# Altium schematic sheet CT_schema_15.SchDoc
size 391 x 385 mm
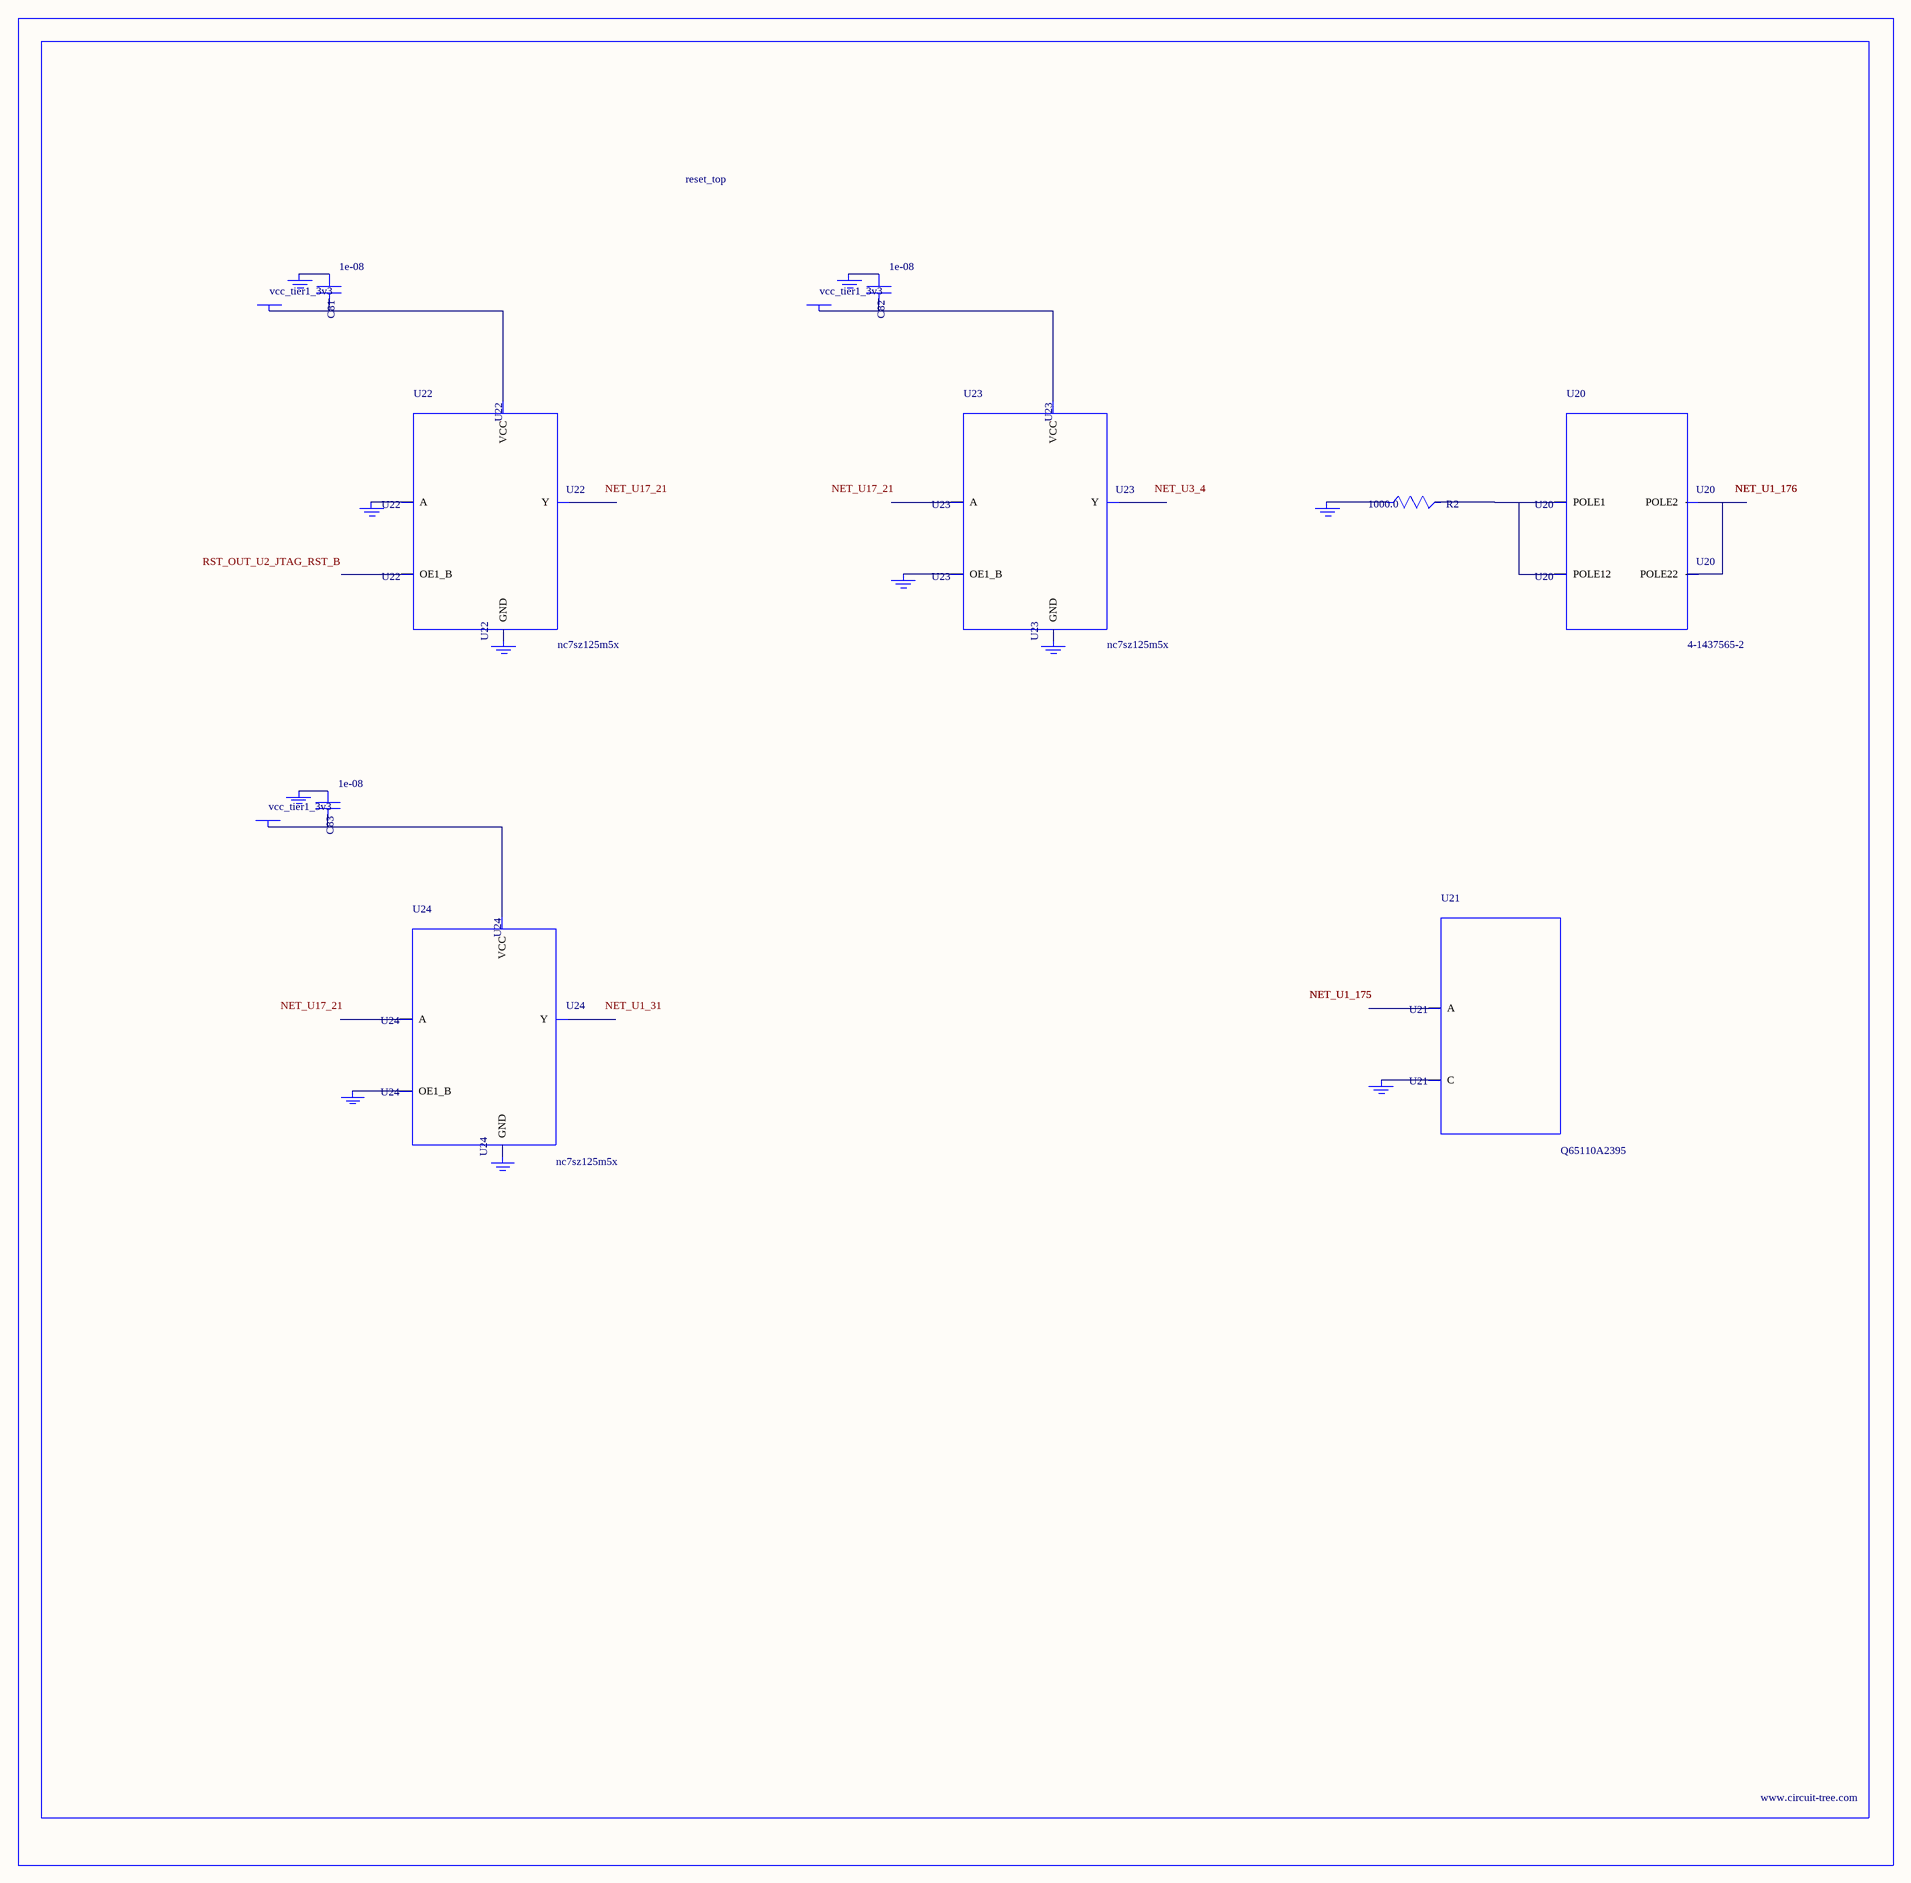
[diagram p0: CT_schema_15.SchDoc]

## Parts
BORDER14  (no value)
C81  1e-08  [C0402]
C82  1e-08  [C0402]
C83  1e-08  [C0402]
GND_INSTANCE_14_0  (no value)
GND_INSTANCE_14_1  (no value)
GND_INSTANCE_14_2  (no value)
GND_INSTANCE_14_3  (no value)
GND_INSTANCE_14_4  (no value)
GND_INSTANCE_14_5  (no value)
GND_INSTANCE_14_6  (no value)
GND_INSTANCE_14_7  (no value)
GND_INSTANCE_14_8  (no value)
GND_INSTANCE_14_9  (no value)
GND_INSTANCE_14_10  (no value)
POWER_INSTANCE_14_0  vcc_tier1_3v3
POWER_INSTANCE_14_1  vcc_tier1_3v3
POWER_INSTANCE_14_2  vcc_tier1_3v3
R2  1000.0  [R0603]
U20  4-1437565-2  [SW_4-1437565-2]
U21  Q65110A2395  [LGM67K-G1J2-24-Z]
U22  nc7sz125m5x  [NC7SZ125M5X]
U23  nc7sz125m5x  [NC7SZ125M5X]
U24  nc7sz125m5x  [NC7SZ125M5X]

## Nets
NetC81_1: C81.1 GND_INSTANCE_14_2.0(GND)
NetC81_2: C81.2 POWER_INSTANCE_14_0.0(PWR) U22.5(VCC)
NetC82_1: C82.1 GND_INSTANCE_14_5.0(GND)
NetC82_2: C82.2 POWER_INSTANCE_14_1.0(PWR) U23.5(VCC)
NetC83_1: C83.1 GND_INSTANCE_14_8.0(GND)
NetC83_2: C83.2 POWER_INSTANCE_14_2.0(PWR) U24.5(VCC)
NetGND_INSTANCE_14_0_0: GND_INSTANCE_14_0.0(GND) R2.1
NetGND_INSTANCE_14_1_0: GND_INSTANCE_14_1.0(GND) U21.C
NetGND_INSTANCE_14_3_0: GND_INSTANCE_14_3.0(GND) U22.2(A)
NetGND_INSTANCE_14_4_0: GND_INSTANCE_14_4.0(GND) U22.3(GND)
NetGND_INSTANCE_14_6_0: GND_INSTANCE_14_6.0(GND) U23.1(OE1_B)
NetGND_INSTANCE_14_7_0: GND_INSTANCE_14_7.0(GND) U23.3(GND)
NetGND_INSTANCE_14_9_0: GND_INSTANCE_14_9.0(GND) U24.1(OE1_B)
NetGND_INSTANCE_14_10_0: GND_INSTANCE_14_10.0(GND) U24.3(GND)
NetR2_2: R2.2 U20.1(POLE1) U20.2(POLE12)
NetU20_3: U20.3(POLE2) U20.4(POLE22)

Not connected (* = marked no-connect by the designer): U21 A; U22 1(OE1_B) 4(Y); U23 2(A) 4(Y); U24 2(A) 4(Y)

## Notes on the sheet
- Labels drawn without touching a wire or pin: NET_U1_31, NET_U3_4, NET_U17_21, RST_OUT_U2_JTAG_RST_B

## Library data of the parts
BORDER14 = BORDER_PAGE14
C81-C83 = C0402C103K3RAC
GND_INSTANCE_14_0-GND_INSTANCE_14_10 = GND
POWER_INSTANCE_14_0-POWER_INSTANCE_14_2 = PWR
R2 = RC0603JR-071KL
